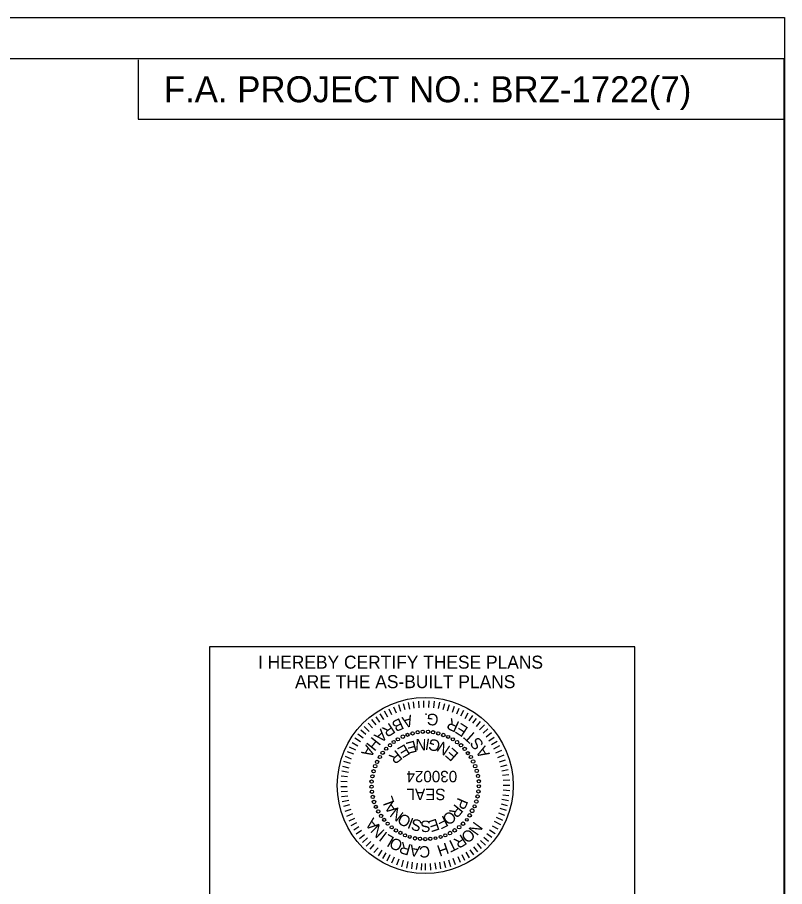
# Model space of a CAD drawing. Extents: x 985 to 1514, y -701 to -21.
# Drawn here: x 1204.2 to 1263.2, y -111.7 to -44.9 of the extents above; entities that cross this region are included whole.
import ezdxf

# ---------------------------------------------------------------- set-up
doc = ezdxf.new("R2010")
doc.units = 0
for name, color, linetype in [('Peseal', 7, 'Continuous'), ('Plan Sheet CELL', 7, 'Continuous'), ('Plot Shape CELL', 7, 'Continuous'), ('Text', 7, 'Continuous'), ('Title Text', 7, 'Continuous'), ('User Information Notes', 7, 'Continuous')]:
    doc.layers.add(name, color=color, linetype=linetype)

msp = doc.modelspace()

# ---------------------------------------------------------------- linework, layer by layer
at = {"layer": 'Peseal'}
for p, q in [((1234.74, -98.022), (1234.678, -97.522)), ((1235.115, -97.99), (1235.084, -97.49)), ((1235.49, -97.959), (1235.49, -97.459)), ((1235.865, -97.959), (1235.896, -97.459)), ((1236.24, -97.99), (1236.303, -97.49)), ((1233.021, -98.522), (1232.803, -98.084)), ((1233.365, -98.397), (1233.178, -97.928)), ((1233.709, -98.272), (1233.553, -97.772)), ((1234.053, -98.147), (1233.928, -97.678)), ((1234.396, -98.084), (1234.303, -97.584)), ((1236.615, -98.053), (1236.709, -97.553)), ((1236.959, -98.115), (1237.084, -97.647)), ((1237.303, -98.209), (1237.459, -97.74)), ((1237.678, -98.334), (1237.834, -97.865)), ((1238.021, -98.459), (1238.209, -98.022)), ((1238.334, -98.615), (1238.553, -98.178)), ((1232.084, -99.084), (1231.803, -98.678)), ((1232.396, -98.897), (1232.115, -98.459)), ((1232.709, -98.709), (1232.459, -98.24)), ((1238.646, -98.803), (1238.897, -98.365)), ((1238.959, -98.99), (1239.24, -98.584)), ((1239.24, -99.178), (1239.522, -98.803)), ((1231.271, -99.803), (1230.896, -99.428)), ((1231.521, -99.522), (1231.209, -99.178)), ((1231.803, -99.303), (1231.49, -98.897)), ((1239.522, -99.428), (1239.834, -99.053)), ((1239.772, -99.678), (1240.147, -99.303)), ((1230.803, -100.334), (1230.396, -100.022)), ((1231.021, -100.053), (1230.646, -99.709)), ((1240.053, -99.928), (1240.397, -99.615)), ((1240.272, -100.209), (1240.678, -99.897)), ((1230.396, -100.928), (1229.959, -100.678)), ((1230.615, -100.615), (1230.178, -100.334)), ((1240.49, -100.522), (1240.897, -100.24)), ((1240.678, -100.803), (1241.115, -100.553)), ((1230.084, -101.553), (1229.615, -101.366)), ((1230.24, -101.241), (1229.771, -101.022)), ((1240.865, -101.147), (1241.334, -100.897)), ((1241.022, -101.459), (1241.49, -101.241)), ((1229.834, -102.272), (1229.334, -102.116)), ((1229.928, -101.928), (1229.459, -101.741)), ((1241.178, -101.803), (1241.647, -101.616)), ((1241.303, -102.147), (1241.772, -101.991)), ((1229.678, -102.959), (1229.178, -102.866)), ((1229.74, -102.616), (1229.24, -102.491)), ((1241.397, -102.491), (1241.897, -102.366)), ((1241.49, -102.834), (1241.959, -102.741)), ((1229.615, -103.303), (1229.115, -103.241)), ((1241.522, -103.178), (1242.022, -103.116)), ((1241.584, -103.553), (1242.084, -103.522)), ((1229.584, -103.678), (1229.084, -103.647)), ((1229.584, -104.053), (1229.084, -104.053)), ((1241.584, -103.928), (1242.084, -103.928)), ((1229.615, -104.428), (1229.115, -104.459)), ((1229.646, -104.772), (1229.146, -104.834)), ((1241.553, -104.678), (1242.022, -104.741)), ((1241.584, -104.303), (1242.084, -104.334)), ((1229.709, -105.116), (1229.209, -105.209)), ((1229.771, -105.459), (1229.303, -105.584)), ((1241.428, -105.366), (1241.897, -105.491)), ((1241.49, -105.022), (1241.99, -105.116)), ((1229.865, -105.803), (1229.396, -105.959)), ((1229.99, -106.147), (1229.521, -106.334)), ((1241.209, -106.053), (1241.678, -106.241)), ((1241.334, -105.709), (1241.803, -105.866)), ((1230.146, -106.491), (1229.709, -106.709)), ((1230.303, -106.834), (1229.865, -107.053)), ((1240.897, -106.709), (1241.365, -106.959)), ((1241.053, -106.397), (1241.522, -106.616)), ((1230.49, -107.147), (1230.084, -107.397)), ((1230.678, -107.428), (1230.271, -107.709)), ((1240.522, -107.366), (1240.959, -107.647)), ((1240.74, -107.053), (1241.178, -107.303)), ((1230.928, -107.741), (1230.521, -108.053)), ((1231.146, -107.991), (1230.771, -108.334)), ((1239.834, -108.178), (1240.209, -108.553)), ((1240.084, -107.928), (1240.459, -108.241)), ((1240.334, -107.647), (1240.709, -107.928)), ((1231.396, -108.272), (1231.053, -108.616)), ((1231.646, -108.491), (1231.334, -108.866)), ((1231.959, -108.741), (1231.646, -109.116)), ((1239.022, -108.897), (1239.303, -109.303)), ((1239.303, -108.678), (1239.615, -109.053)), ((1239.584, -108.428), (1239.897, -108.803)), ((1232.24, -108.928), (1231.959, -109.366)), ((1232.553, -109.147), (1232.303, -109.584)), ((1232.865, -109.303), (1232.646, -109.772)), ((1233.209, -109.459), (1232.99, -109.928)), ((1237.709, -109.553), (1237.896, -110.022)), ((1238.084, -109.428), (1238.271, -109.866)), ((1238.396, -109.272), (1238.615, -109.709)), ((1238.709, -109.084), (1238.959, -109.522)), ((1233.553, -109.616), (1233.365, -110.084)), ((1233.896, -109.709), (1233.771, -110.209)), ((1234.24, -109.803), (1234.146, -110.303)), ((1234.584, -109.866), (1234.521, -110.366)), ((1234.959, -109.928), (1234.896, -110.428)), ((1235.303, -109.959), (1235.271, -110.459)), ((1235.584, -109.959), (1235.584, -110.459)), ((1235.959, -109.959), (1235.99, -110.459)), ((1236.334, -109.897), (1236.396, -110.397)), ((1236.678, -109.866), (1236.771, -110.366)), ((1237.021, -109.772), (1237.146, -110.272)), ((1237.365, -109.678), (1237.521, -110.178))]:
    msp.add_line(p, q, dxfattribs=at)
for centre, radius in [((1233.865, -100.209), 0.14), ((1234.225, -100.069), 0.119), ((1234.615, -99.959), 0.129), ((1235.006, -99.865), 0.126), ((1235.396, -99.834), 0.125), ((1235.803, -99.834), 0.125), ((1236.193, -99.865), 0.126), ((1236.584, -99.959), 0.129), ((1236.975, -100.084), 0.134), ((1237.35, -100.225), 0.119), ((1232.881, -100.866), 0.122), ((1233.162, -100.616), 0.122), ((1233.49, -100.412), 0.126), ((1237.709, -100.412), 0.126), ((1238.037, -100.631), 0.134), ((1238.334, -100.866), 0.133), ((1232.318, -101.444), 0.134), ((1232.584, -101.131), 0.122), ((1238.615, -101.147), 0.133), ((1238.865, -101.475), 0.122), ((1231.881, -102.147), 0.126), ((1232.1, -101.772), 0.126), ((1239.1, -101.772), 0.126), ((1239.271, -102.116), 0.14), ((1231.615, -102.866), 0.129), ((1231.74, -102.475), 0.134), ((1239.428, -102.475), 0.134), ((1239.553, -102.834), 0.129), ((1231.459, -103.662), 0.126), ((1231.521, -103.256), 0.126), ((1239.646, -103.225), 0.126), ((1239.709, -103.631), 0.126), ((1231.459, -104.053), 0.125), ((1239.709, -104.022), 0.125), ((1231.49, -104.444), 0.126), ((1231.553, -104.834), 0.129), ((1239.615, -104.803), 0.129), ((1239.678, -104.412), 0.126), ((1231.646, -105.225), 0.134), ((1231.787, -105.6), 0.119), ((1239.381, -105.569), 0.119), ((1239.521, -105.194), 0.134), ((1231.975, -105.959), 0.126), ((1232.193, -106.303), 0.126), ((1239.006, -106.256), 0.134), ((1239.193, -105.897), 0.144), ((1232.428, -106.6), 0.122), ((1232.693, -106.897), 0.122), ((1238.49, -106.897), 0.133), ((1238.787, -106.6), 0.11), ((1233.006, -107.178), 0.122), ((1233.334, -107.412), 0.126), ((1233.678, -107.6), 0.126), ((1237.49, -107.616), 0.14), ((1237.85, -107.412), 0.134), ((1238.193, -107.162), 0.134), ((1234.037, -107.787), 0.119), ((1234.396, -107.912), 0.114), ((1234.803, -108.022), 0.129), ((1235.193, -108.053), 0.126), ((1235.584, -108.084), 0.125), ((1235.975, -108.053), 0.126), ((1236.381, -108.006), 0.11), ((1236.771, -107.912), 0.114), ((1237.131, -107.787), 0.119)]:
    msp.add_circle(centre, radius, dxfattribs=at)
at = {"layer": 'Plan Sheet CELL'}
for p, q in [((1263.227, -44.917), (1263.227, -44.917)), ((1007.154, -48.069), (1263.157, -48.069)), ((1263.157, -48.069), (1263.157, -216.068)), ((1213.502, -48.181), (1213.502, -52.743)), ((1213.502, -52.743), (1263.157, -52.743))]:
    msp.add_line(p, q, dxfattribs=at)
msp.add_lwpolyline([(1218.983, -115.31), (1251.715, -115.31), (1251.715, -93.31), (1218.983, -93.31)], close=True, dxfattribs=at)
at = {"layer": 'Plot Shape CELL'}
msp.add_lwpolyline([(998.722, -44.917), (1263.227, -44.917), (1263.227, -220.917), (998.722, -220.917)], close=True, dxfattribs=at)
at = {"layer": 'User Information Notes'}
msp.add_line((1235.584, -103.959), (1235.584, -103.959), dxfattribs=at)
msp.add_circle((1235.584, -103.959), 6.766, dxfattribs=at)

# ---------------------------------------------------------------- texts
at = {"layer": 'Peseal'}
for s, height, rotation, p in [('B', 0.887, 204.83116, (1233.654, -98.749)), ('A', 0.887, 195.79553, (1234.497, -98.511)), ('.', 0.887, 182.13226, (1235.814, -98.408)), ('G', 0.887, 173.38579, (1236.656, -98.508)), ('R', 0.888, 155.458, (1238.282, -99.103)), ('R', 0.887, 213.57762, (1232.885, -99.103)), ('E', 0.887, 147.14527, (1238.955, -99.544)), ('A', 0.887, 222.32409, (1232.178, -99.57)), ('T', 0.887, 138.10965, (1239.607, -100.128)), ('A', 0.887, 239.60072, (1231.028, -100.78)), ('H', 0.887, 231.35972, (1231.531, -100.16)), ('E', 0.875, 210.68151, (1234.053, -100.74)), ('E', 0.875, 194.64516, (1234.803, -100.49)), ('N', 0.875, 178.60881, (1235.678, -100.397)), ('I', 0.875, 170.59064, (1235.99, -100.397)), ('G', 0.875, 162.57247, (1236.834, -100.584)), ('N', 0.875, 146.53612, (1237.584, -100.991)), ('S', 0.887, 129.43491, (1240.139, -100.779)), ('A', 0.887, 120.39928, (1240.582, -101.533)), ('R', 0.875, 218.69968, (1233.365, -101.178)), ('E', 0.875, 138.51794, (1238.209, -101.522)), ('030024', 0.8751, 180, (1238.044, -102.834)), ('SEAL', 0.8751, 180, (1237.146, -104.209)), ('L', 0.875, 110.08236, (1233.24, -105.303)), ('A', 0.875, 126.14825, (1233.553, -105.741)), ('R', 0.875, 230.57654, (1237.896, -105.334)), ('P', 0.875, 246.64243, (1238.115, -104.834)), ('N', 0.875, 142.21414, (1233.99, -106.116)), ('O', 0.875, 150.24709, (1234.584, -106.491)), ('O', 0.875, 222.54359, (1237.49, -105.834)), ('A', 0.875, 128.64767, (1232.084, -106.991)), ('I', 0.875, 158.28003, (1234.771, -106.522)), ('S', 0.875, 166.31297, (1235.396, -106.678)), ('S', 0.875, 182.37887, (1235.99, -106.647)), ('E', 0.875, 198.44476, (1236.49, -106.491)), ('F', 0.875, 206.4777, (1237.053, -106.241)), ('N', 0.875, 234.05043, (1239.365, -106.678)), ('N', 0.875, 135.67452, (1232.521, -107.459)), ('I', 0.875, 142.70138, (1232.74, -107.647)), ('O', 0.875, 219.99672, (1238.959, -107.209)), ('L', 0.875, 149.72823, (1233.271, -107.991)), ('O', 0.875, 156.75507, (1233.928, -108.272)), ('T', 0.875, 205.94303, (1237.803, -108.022)), ('R', 0.875, 212.96988, (1238.396, -107.678)), ('R', 0.875, 163.78193, (1234.553, -108.522)), ('A', 0.875, 170.80877, (1235.24, -108.616)), ('C', 0.875, 184.86247, (1235.928, -108.584)), ('H', 0.875, 198.91617, (1237.209, -108.334))]:
    msp.add_text(s, height=height, rotation=rotation, dxfattribs=at).set_placement(p)
at = {"layer": 'Text'}
for s, p in [('I HEREBY CERTIFY THESE PLANS', (1222.725, -94.98)), ('ARE THE AS-BUILT PLANS', (1225.576, -96.48))]:
    msp.add_text(s, height=1, dxfattribs=at).set_placement(p)
at = {"layer": 'Title Text'}
msp.add_text('F.A. PROJECT NO.: BRZ-1722(7)', height=2, dxfattribs=at).set_placement((1215.482, -51.441))

doc.saveas('drawing.dxf')
